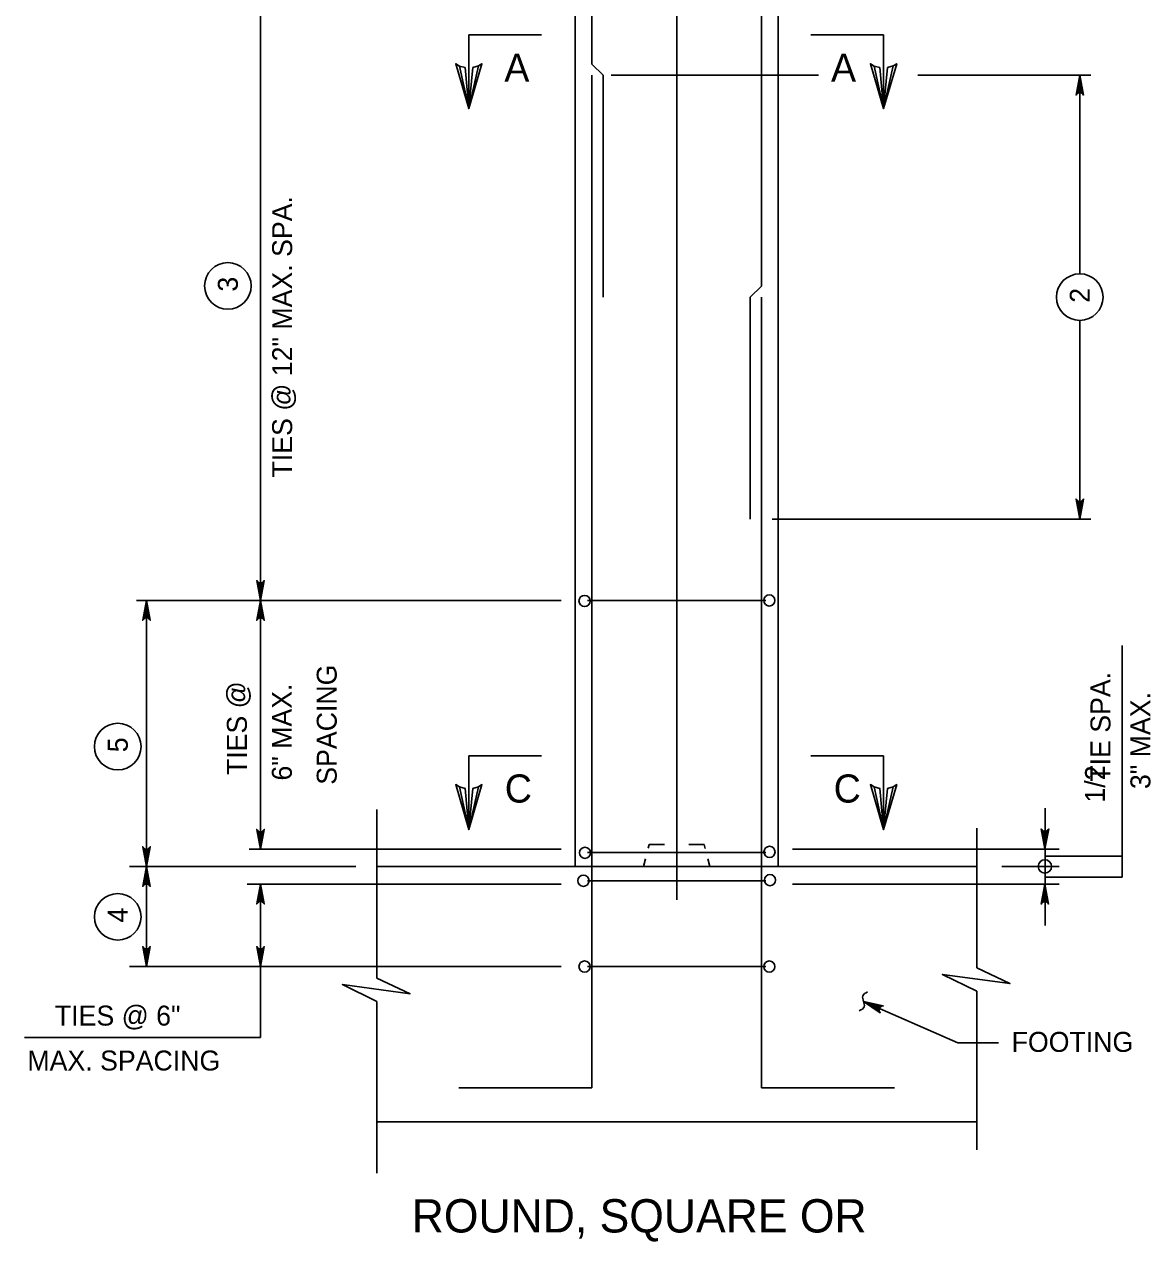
# Model space of a CAD drawing. Extents: x 646165 to 651486, y 296916 to 299292.
# Drawn here: x 648370.3 to 648539.5, y 297798.2 to 297981.1 of the extents above; entities that cross this region are included whole.
import ezdxf

# ---------------------------------------------------------------- set-up
doc = ezdxf.new("R2010")
doc.units = 0
for name, color, linetype in [('1', 7, 'Continuous'), ('50', 7, 'Continuous'), ('51', 7, 'Continuous'), ('52', 7, 'Continuous'), ('53', 7, 'Continuous'), ('54', 7, 'Continuous'), ('57', 7, 'Continuous')]:
    doc.layers.add(name, color=color, linetype=linetype)

msp = doc.modelspace()

# ---------------------------------------------------------------- linework, layer by layer
at = {"layer": '1'}
for p, q in [((648437.03, 297968.47), (648437.03, 297979.54)), ((648437.03, 297979.54), (648447.96, 297979.54)), ((648499.35, 297979.54), (648488.43, 297979.54)), ((648499.35, 297968.47), (648499.35, 297979.54)), ((648437.03, 297860.15), (648437.03, 297871.22)), ((648437.03, 297871.22), (648447.96, 297871.22)), ((648499.35, 297871.22), (648488.43, 297871.22)), ((648499.35, 297860.15), (648499.35, 297871.22))]:
    msp.add_line(p, q, dxfattribs=at)
for points in [[(648438.51, 297974.89), (648437.66, 297974.65), (648437.03, 297968.47), (648438.51, 297974.89), (648439.02, 297975.22), (648437.03, 297968.47), (648436.48, 297974.65), (648435.64, 297974.87), (648437.03, 297968.47), (648435.08, 297975.22), (648435.64, 297974.87)], [(648500.82, 297974.89), (648499.97, 297974.65), (648499.35, 297968.47), (648500.82, 297974.89), (648501.34, 297975.22), (648499.35, 297968.47), (648498.79, 297974.65), (648497.96, 297974.87), (648499.35, 297968.47), (648497.4, 297975.22), (648497.96, 297974.87)], [(648438.51, 297866.57), (648437.66, 297866.33), (648437.03, 297860.15), (648438.51, 297866.57), (648439.02, 297866.9), (648437.03, 297860.15), (648436.48, 297866.33), (648435.64, 297866.55), (648437.03, 297860.15), (648435.08, 297866.9), (648435.64, 297866.55)], [(648500.82, 297866.57), (648499.97, 297866.33), (648499.35, 297860.15), (648500.82, 297866.57), (648501.34, 297866.9), (648499.35, 297860.15), (648498.79, 297866.33), (648497.96, 297866.55), (648499.35, 297860.15), (648497.4, 297866.9), (648497.96, 297866.55)]]:
    msp.add_lwpolyline(points, dxfattribs=at)
at = {"layer": '50'}
msp.add_line((648468.28, 298030.72), (648468.28, 297849.57), dxfattribs=at)
at = {"layer": '51'}
for p, q in [((648453.04, 298025.72), (648453.04, 297854.57)), ((648483.51, 298025.72), (648483.51, 297854.57)), ((648463.99, 297857.34), (648464.14, 297857.92)), ((648464.14, 297857.92), (648466.46, 297857.92)), ((648470.11, 297857.92), (648472.41, 297857.92)), ((648472.58, 297857.28), (648472.41, 297857.92)), ((648463.28, 297854.57), (648463.59, 297855.77)), ((648473.28, 297854.57), (648472.97, 297855.77)), ((648423.25, 297854.57), (648513.39, 297854.57)), ((648423.25, 297816.24), (648513.39, 297816.24))]:
    msp.add_line(p, q, dxfattribs=at)
at = {"layer": '52'}
for p, q in [((648405.75, 298023.11), (648405.75, 297857.18)), ((648489.59, 297973.48), (648458.44, 297973.48)), ((648530.5, 297973.48), (648504.51, 297973.48)), ((648528.85, 297973.48), (648528.85, 297943.65)), ((648528.85, 297936.65), (648528.85, 297906.81)), ((648530.5, 297906.81), (648482.65, 297906.81)), ((648387.11, 297894.57), (648450.9, 297894.57)), ((648388.61, 297894.57), (648388.61, 297839.57)), ((648535.2, 297887.79), (648535.2, 297853)), ((648423.25, 297863.18), (648423.25, 297837.83)), ((648523.63, 297863.36), (648523.63, 297845.74)), ((648513.39, 297860.34), (648513.39, 297839.36)), ((648404.05, 297857.18), (648450.9, 297857.18)), ((648485.66, 297857.18), (648525.76, 297857.18)), ((648523.67, 297856.14), (648535.2, 297856.14)), ((648386.08, 297854.57), (648420.09, 297854.57)), ((648517.14, 297854.57), (648525.76, 297854.57)), ((648523.67, 297853), (648535.2, 297853)), ((648403.76, 297851.95), (648450.9, 297851.95)), ((648405.75, 297851.95), (648405.75, 297828.89)), ((648485.66, 297851.95), (648525.76, 297851.95)), ((648386.08, 297839.57), (648450.9, 297839.57)), ((648513.39, 297835.84), (648513.39, 297812.01)), ((648423.25, 297834.31), (648423.25, 297808.51)), ((648510.53, 297828.1), (648496.36, 297834.33)), ((648370.26, 297828.89), (648405.75, 297828.89)), ((648510.53, 297828.1), (648516.62, 297828.1))]:
    msp.add_line(p, q, dxfattribs=at)
for points in [[(648528.85, 297973.48), (648529.41, 297970.5), (648529.25, 297970.73), (648529.05, 297970.85), (648528.85, 297970.88), (648528.65, 297970.85), (648528.45, 297970.73), (648528.29, 297970.5), (648528.85, 297973.48), (648528.45, 297970.73), (648528.65, 297970.85), (648528.85, 297973.48), (648528.85, 297970.88), (648529.05, 297970.85), (648528.85, 297973.48), (648529.25, 297970.73)], [(648528.85, 297906.81), (648528.29, 297909.8), (648528.45, 297909.57), (648528.65, 297909.45), (648528.85, 297909.41), (648529.05, 297909.45), (648529.25, 297909.57), (648529.41, 297909.8), (648528.85, 297906.81), (648529.25, 297909.57), (648529.05, 297909.45), (648528.85, 297906.81), (648528.85, 297909.41), (648528.65, 297909.45), (648528.85, 297906.81), (648528.45, 297909.57)], [(648405.75, 297894.57), (648406.31, 297897.55), (648406.15, 297897.32), (648405.95, 297897.2), (648405.75, 297897.17), (648405.55, 297897.2), (648405.35, 297897.32), (648405.19, 297897.55), (648405.75, 297894.57), (648405.35, 297897.32), (648405.55, 297897.2), (648405.75, 297894.57), (648405.75, 297897.17), (648405.95, 297897.2), (648405.75, 297894.57), (648406.15, 297897.32)], [(648388.61, 297894.57), (648389.17, 297891.59), (648389.09, 297891.7), (648389.01, 297891.82), (648388.91, 297891.88), (648388.81, 297891.94), (648388.71, 297891.95), (648388.61, 297891.97), (648388.51, 297891.95), (648388.41, 297891.94), (648388.31, 297891.88), (648388.21, 297891.82), (648388.13, 297891.7), (648388.05, 297891.59), (648388.61, 297894.57), (648388.13, 297891.7), (648388.21, 297891.82), (648388.61, 297894.57), (648388.31, 297891.88), (648388.41, 297891.94), (648388.61, 297894.57), (648388.51, 297891.95), (648388.61, 297891.97), (648388.61, 297894.57), (648388.71, 297891.95), (648388.81, 297891.94), (648388.61, 297894.57), (648388.91, 297891.88), (648389.01, 297891.82), (648388.61, 297894.57), (648389.09, 297891.7)], [(648405.75, 297894.57), (648406.31, 297891.59), (648406.15, 297891.82), (648405.95, 297891.94), (648405.75, 297891.97), (648405.55, 297891.94), (648405.35, 297891.82), (648405.19, 297891.59), (648405.75, 297894.57), (648405.35, 297891.82), (648405.55, 297891.94), (648405.75, 297894.57), (648405.75, 297891.97), (648405.95, 297891.94), (648405.75, 297894.57), (648406.15, 297891.82)], [(648523.62, 297857.26), (648523.07, 297860.25), (648523.15, 297860.13), (648523.22, 297860.02), (648523.32, 297859.96), (648523.42, 297859.9), (648523.52, 297859.88), (648523.62, 297859.86), (648523.72, 297859.88), (648523.82, 297859.9), (648523.92, 297859.96), (648524.02, 297860.02), (648524.1, 297860.13), (648524.18, 297860.25), (648523.62, 297857.26), (648524.1, 297860.13), (648524.02, 297860.02), (648523.62, 297857.26), (648523.92, 297859.96), (648523.82, 297859.9), (648523.62, 297857.26), (648523.72, 297859.88), (648523.62, 297859.86), (648523.62, 297857.26), (648523.52, 297859.88), (648523.42, 297859.9), (648523.62, 297857.26), (648523.32, 297859.96), (648523.22, 297860.02), (648523.62, 297857.26), (648523.15, 297860.13)], [(648405.75, 297857.18), (648405.19, 297860.17), (648405.27, 297860.05), (648405.35, 297859.94), (648405.45, 297859.88), (648405.55, 297859.82), (648405.65, 297859.8), (648405.75, 297859.78), (648405.85, 297859.8), (648405.95, 297859.82), (648406.05, 297859.88), (648406.15, 297859.94), (648406.23, 297860.05), (648406.31, 297860.17), (648405.75, 297857.18), (648406.23, 297860.05), (648406.15, 297859.94), (648405.75, 297857.18), (648406.05, 297859.88), (648405.95, 297859.82), (648405.75, 297857.18), (648405.85, 297859.8), (648405.75, 297859.78), (648405.75, 297857.18), (648405.65, 297859.8), (648405.55, 297859.82), (648405.75, 297857.18), (648405.45, 297859.88), (648405.35, 297859.94), (648405.75, 297857.18), (648405.27, 297860.05)], [(648388.61, 297854.57), (648389.17, 297857.55), (648389.09, 297857.44), (648389.01, 297857.32), (648388.91, 297857.26), (648388.81, 297857.2), (648388.71, 297857.19), (648388.61, 297857.17), (648388.51, 297857.19), (648388.41, 297857.2), (648388.31, 297857.26), (648388.21, 297857.32), (648388.13, 297857.44), (648388.05, 297857.55), (648388.61, 297854.57), (648388.13, 297857.44), (648388.21, 297857.32), (648388.61, 297854.57), (648388.31, 297857.26), (648388.41, 297857.2), (648388.61, 297854.57), (648388.51, 297857.19), (648388.61, 297857.17), (648388.61, 297854.57), (648388.71, 297857.19), (648388.81, 297857.2), (648388.61, 297854.57), (648388.91, 297857.26), (648389.01, 297857.32), (648388.61, 297854.57), (648389.09, 297857.44)], [(648388.61, 297854.57), (648389.17, 297851.59), (648389.09, 297851.7), (648389.01, 297851.82), (648388.91, 297851.88), (648388.81, 297851.93), (648388.71, 297851.95), (648388.61, 297851.97), (648388.51, 297851.95), (648388.41, 297851.93), (648388.31, 297851.88), (648388.21, 297851.82), (648388.13, 297851.7), (648388.05, 297851.59), (648388.61, 297854.57), (648388.13, 297851.7), (648388.21, 297851.82), (648388.61, 297854.57), (648388.31, 297851.88), (648388.41, 297851.93), (648388.61, 297854.57), (648388.51, 297851.95), (648388.61, 297851.97), (648388.61, 297854.57), (648388.71, 297851.95), (648388.81, 297851.93), (648388.61, 297854.57), (648388.91, 297851.88), (648389.01, 297851.82), (648388.61, 297854.57), (648389.09, 297851.7)], [(648405.75, 297851.95), (648406.31, 297848.97), (648406.23, 297849.09), (648406.15, 297849.2), (648406.05, 297849.26), (648405.95, 297849.32), (648405.85, 297849.34), (648405.75, 297849.35), (648405.65, 297849.34), (648405.55, 297849.32), (648405.45, 297849.26), (648405.35, 297849.2), (648405.27, 297849.09), (648405.19, 297848.97), (648405.75, 297851.95), (648405.27, 297849.09), (648405.35, 297849.2), (648405.75, 297851.95), (648405.45, 297849.26), (648405.55, 297849.32), (648405.75, 297851.95), (648405.65, 297849.34), (648405.75, 297849.35), (648405.75, 297851.95), (648405.85, 297849.34), (648405.95, 297849.32), (648405.75, 297851.95), (648406.05, 297849.26), (648406.15, 297849.2), (648405.75, 297851.95), (648406.23, 297849.09)], [(648523.61, 297851.92), (648524.17, 297848.94), (648524.09, 297849.06), (648524.01, 297849.17), (648523.91, 297849.23), (648523.81, 297849.29), (648523.71, 297849.31), (648523.61, 297849.32), (648523.51, 297849.31), (648523.41, 297849.29), (648523.31, 297849.23), (648523.21, 297849.17), (648523.13, 297849.06), (648523.05, 297848.94), (648523.61, 297851.92), (648523.13, 297849.06), (648523.21, 297849.17), (648523.61, 297851.92), (648523.31, 297849.23), (648523.41, 297849.29), (648523.61, 297851.92), (648523.51, 297849.31), (648523.61, 297849.32), (648523.61, 297851.92), (648523.71, 297849.31), (648523.81, 297849.29), (648523.61, 297851.92), (648523.91, 297849.23), (648524.01, 297849.17), (648523.61, 297851.92), (648524.09, 297849.06)], [(648388.61, 297839.57), (648388.05, 297842.55), (648388.13, 297842.44), (648388.21, 297842.32), (648388.31, 297842.26), (648388.41, 297842.2), (648388.51, 297842.19), (648388.61, 297842.17), (648388.71, 297842.19), (648388.81, 297842.2), (648388.91, 297842.26), (648389.01, 297842.32), (648389.09, 297842.44), (648389.17, 297842.55), (648388.61, 297839.57), (648389.09, 297842.44), (648389.01, 297842.32), (648388.61, 297839.57), (648388.91, 297842.26), (648388.81, 297842.2), (648388.61, 297839.57), (648388.71, 297842.19), (648388.61, 297842.17), (648388.61, 297839.57), (648388.51, 297842.19), (648388.41, 297842.2), (648388.61, 297839.57), (648388.31, 297842.26), (648388.21, 297842.32), (648388.61, 297839.57), (648388.13, 297842.44)], [(648405.75, 297839.57), (648405.19, 297842.55), (648405.27, 297842.44), (648405.35, 297842.32), (648405.45, 297842.26), (648405.55, 297842.2), (648405.65, 297842.19), (648405.75, 297842.17), (648405.85, 297842.19), (648405.95, 297842.2), (648406.05, 297842.26), (648406.15, 297842.32), (648406.23, 297842.44), (648406.31, 297842.55), (648405.75, 297839.57), (648406.23, 297842.44), (648406.15, 297842.32), (648405.75, 297839.57), (648406.05, 297842.26), (648405.95, 297842.2), (648405.75, 297839.57), (648405.85, 297842.19), (648405.75, 297842.17), (648405.75, 297839.57), (648405.65, 297842.19), (648405.55, 297842.2), (648405.75, 297839.57), (648405.45, 297842.26), (648405.35, 297842.32), (648405.75, 297839.57), (648405.27, 297842.44)], [(648405.75, 297839.57), (648405.19, 297842.55), (648405.27, 297842.44), (648405.35, 297842.32), (648405.45, 297842.26), (648405.55, 297842.2), (648405.65, 297842.19), (648405.75, 297842.17), (648405.85, 297842.19), (648405.95, 297842.2), (648406.05, 297842.26), (648406.15, 297842.32), (648406.23, 297842.44), (648406.31, 297842.55), (648405.75, 297839.57), (648406.23, 297842.44), (648406.15, 297842.32), (648405.75, 297839.57), (648406.05, 297842.26), (648405.95, 297842.2), (648405.75, 297839.57), (648405.85, 297842.19), (648405.75, 297842.17), (648405.75, 297839.57), (648405.65, 297842.19), (648405.55, 297842.2), (648405.75, 297839.57), (648405.45, 297842.26), (648405.35, 297842.32), (648405.75, 297839.57), (648405.27, 297842.44)], [(648513.39, 297835.84), (648508.2, 297838.37), (648518.35, 297836.99), (648513.39, 297839.36)], [(648423.25, 297834.31), (648418.06, 297836.85), (648428.21, 297835.47), (648423.25, 297837.83)], [(648496.36, 297834.33), (648499.31, 297833.64), (648499.04, 297833.59), (648498.85, 297833.45), (648498.74, 297833.28), (648498.69, 297833.08), (648498.72, 297832.85), (648498.86, 297832.61), (648496.36, 297834.33), (648498.72, 297832.85), (648498.69, 297833.08), (648496.36, 297834.33), (648498.74, 297833.28), (648498.85, 297833.45), (648496.36, 297834.33), (648499.04, 297833.59)]]:
    msp.add_lwpolyline(points, dxfattribs=at)
for centre in [(648400.84, 297941.83), (648528.85, 297940.15), (648384.3, 297872.61), (648384.3, 297847.03)]:
    msp.add_circle(centre, 3.5, dxfattribs=at)
msp.add_spline([(648495.7, 297832.91), (648496.47, 297833.52), (648496.24, 297835.15), (648496.97, 297835.76)], degree=3, dxfattribs=at)
at = {"layer": '54'}
for p, q in [((648455.54, 298050.68), (648455.54, 297975.15)), ((648481.01, 298050.68), (648481.01, 297941.81)), ((648457.21, 297973.48), (648455.54, 297975.15)), ((648455.54, 297973.48), (648455.54, 297821.35)), ((648457.21, 297973.48), (648457.21, 297940.15)), ((648479.34, 297940.15), (648481.01, 297941.81)), ((648479.34, 297940.15), (648479.34, 297906.81)), ((648481.01, 297940.15), (648481.01, 297821.35)), ((648454.88, 297894.57), (648481.68, 297894.57)), ((648454.88, 297856.68), (648481.68, 297856.68)), ((648454.88, 297852.45), (648481.68, 297852.45)), ((648454.88, 297839.57), (648481.68, 297839.57)), ((648435.54, 297821.35), (648455.54, 297821.35)), ((648481.01, 297821.35), (648501.01, 297821.35))]:
    msp.add_line(p, q, dxfattribs=at)
msp.add_circle((648523.61, 297854.6), 1.01, dxfattribs=at)
at = {"layer": '57'}
for centre in [(648454.44, 297894.5), (648482.2, 297894.57), (648454.5, 297856.65), (648482.23, 297856.79), (648454.27, 297852.45), (648482.3, 297852.55), (648454.44, 297839.56), (648482.2, 297839.56)]:
    msp.add_circle(centre, 0.837, dxfattribs=at)

# ---------------------------------------------------------------- texts
at = {"layer": '1'}
for s, p in [('A', (648442.38, 297972.52)), ('A', (648491.47, 297972.52)), ('C', (648442.45, 297864.2)), ('C', (648491.87, 297864.2))]:
    msp.add_text(s, height=4.23, dxfattribs=at).set_placement(p)
at = {"layer": '53'}
for s, p in [('TIES @ 12" MAX. SPA.', (648410.5, 297913.05)), ('3', (648402.34, 297940.98)), ('2', (648530.35, 297939.3)), ('SPACING', (648417.2, 297866.88)), ('   TIE SPA.', (648533.46, 297864)), ('TIES @', (648403.7, 297868.33)), ('6" MAX.', (648410.45, 297867.51)), ('  3" MAX.', (648539.46, 297864)), ('5', (648385.8, 297871.76)), ('1/2', (648532.64, 297864.2)), ('4', (648385.8, 297846.18))]:
    msp.add_text(s, height=3, rotation=90, dxfattribs=at).set_placement(p)
for s, height, p in [('TIES @ 6"', 3, (648374.85, 297830.69)), ('FOOTING', 3, (648518.61, 297826.74)), ('MAX. SPACING', 3, (648370.72, 297823.94)), ('ROUND, SQUARE OR ', 5, (648428.47, 297799.6))]:
    msp.add_text(s, height=height, dxfattribs=at).set_placement(p)

doc.saveas('drawing.dxf')
